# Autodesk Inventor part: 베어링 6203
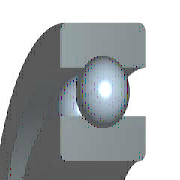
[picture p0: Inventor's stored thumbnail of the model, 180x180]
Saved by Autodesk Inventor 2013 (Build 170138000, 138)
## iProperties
IsCustomPart: 0
Created: 2016-05
Part Number: 베어링 6203
Material: 강, 연강
Description: 깊은 그루브 볼 베어링
Document SubType Name: Modeling
Standard: KS B 2023
Designer: mduedu
Standards Organization: KS
Language: ko-KR
Size Designation: 6203 - 17 x 40 x 12
Categories: <MemberInstance><Categories><Category DisplayName="샤프트 부품" InternalName="7f7aeb1f-a693-4053-b835-cee3144e0d98" Mnemonic="SHFT"><Category DisplayName="베어링" Inter
Density: 1 g/cm^3
Author: mduedu
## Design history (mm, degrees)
sketch "스케치" dims "d0" = 5.98 (= -0.26 x WD + 0.26 x BD)
  geometry: L1 (3.01, 14.25)-(8.99, 14.25); L2 (6, 14.25)-(6, 11.26); L3 (6, 14.25)-(6, 17.24); L4 (3.778, 12.249)-(0, 12.249); L5 (0, 8.5)-(12, 8.5); L6 (3.778, 16.251)-(0, 16.251); L7 (0, 20)-(12, 20); L8 (12, 8.5)-(12, 12.249); L9 (8.222, 12.249)-(12, 12.249); L10 (8.222, 16.251)-(12, 16.251); L11 (12, 20)-(12, 16.251); L12 (-1.4, 0)-(8.4, 0) reference; L13 (0, -0.3)-(0, 5.3) reference
  constraints: 22 end point, 4 point on line, 2 collinear, 2 perpendicular, 2 symmetric about line, 1 midpoint, 1 parallel, 14 other
  dimensions: "d9" = 17 diameter of L5 L12 (= WD); "d11" = 40 diameter of L7 L12 (= BD); "d12" = 12 distance between parallel lines of L8 L13 (= KB); "d13" = 24.498 diameter of L9 L12 (= 0.326 x BD + 0.674 x WD)
revolve "본체" stored, may be unused: angle "d6" = 90 deg
revolve "볼" stored, may be unused: angle "d7" = 90 deg
pattern_circular "IDS_ARRAYBALL[SIMPL:T]" dims angle "d3" = 360 deg
body "Solid1"
fillet "모깎기1" dims "d1" = 0.6 (= KRS)
other parameters: "WD" = 17 [user parameter; used in 5 equation terms], "BD" = 40 [user parameter; used in 5 equation terms], "KB" = 12 [user parameter; used in 1 equation term], "KRS" = 0.6 [user parameter; used in 1 equation term], "d4" = 0, "d5" = 0, "d8" = 0, "d14" = 0, "d15" = 0, "BBA" = 0 [user parameter], "BC0" = 4750000 [user parameter], "BC" = 9560000 [user parameter], "WR" = 8.5 (= 0.5 x WD) [user parameter]
